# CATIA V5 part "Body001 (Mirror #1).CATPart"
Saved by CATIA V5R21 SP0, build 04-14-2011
Part number: Body001 (Mirror #1)
Definition: design
Nomenclature: Body001 (Mirror #1)
Source: Unknown
Bounding box of the stored display mesh (mm): x -0.8 to -0.6, y -0.4 to 0.4, z 0 to 1
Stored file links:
  C:\Users\beatr\OneDrive\Documents\UNB\2026_1\Pi1\Componentes eletronicos\Encoder\Body001 (Mirror #1).CATPart
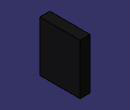
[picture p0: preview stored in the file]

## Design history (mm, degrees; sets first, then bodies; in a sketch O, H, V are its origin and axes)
Body1 "MANIFOLD_SOLID_BREP #4293" (main body)
  Solid1: solid without history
